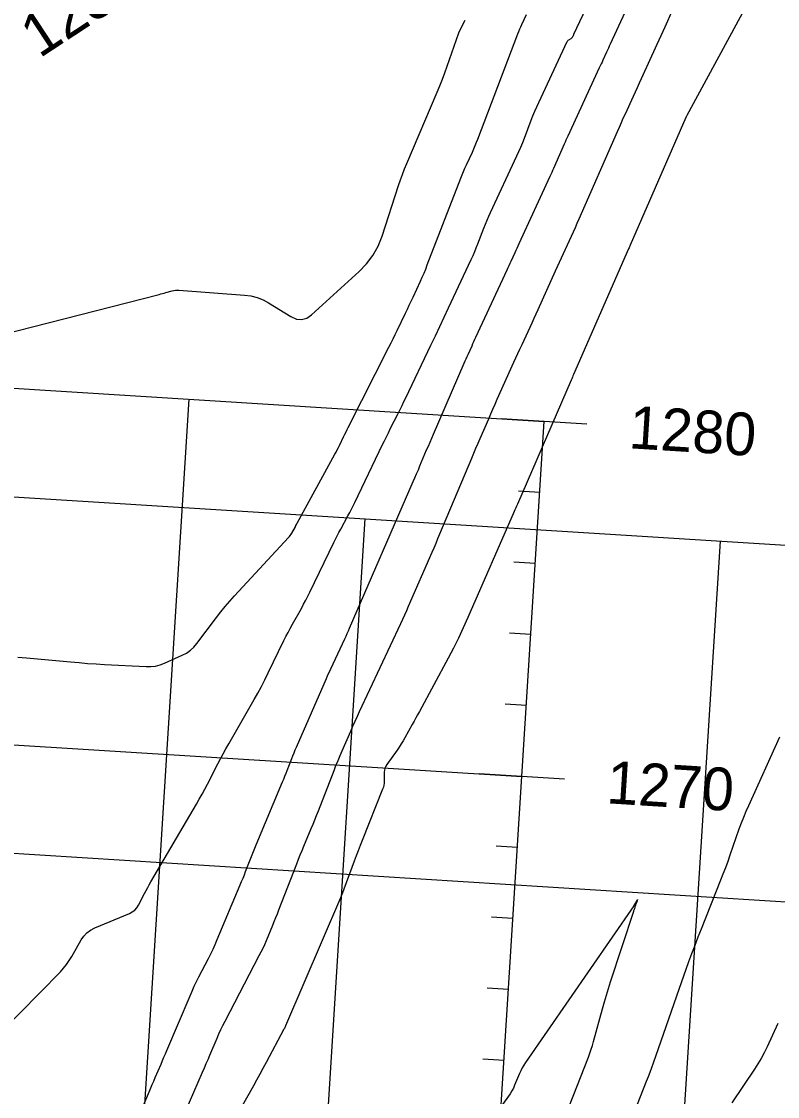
# Model space of a CAD drawing. Extents: x 658976 to 668726, y 639543 to 647196.
# Drawn here: x 661838.3 to 661944.5, y 642005.3 to 642156.4 of the extents above; entities that cross this region are included whole.
import ezdxf

# ---------------------------------------------------------------- set-up
doc = ezdxf.new("R2010")
doc.units = 0
for name, color, linetype in [('Ex_Contour Labels', 7, 'Continuous'), ('Ex_Major Contours', 7, 'Continuous'), ('Ex_Minor Contours', 7, 'Continuous'), ('R_Axis', 7, 'Continuous'), ('R_Axis Annot', 7, 'Continuous'), ('R_Grid', 7, 'Continuous')]:
    doc.layers.add(name, color=color, linetype=linetype)

msp = doc.modelspace()

# ---------------------------------------------------------------- linework, layer by layer
at = {"layer": 'Ex_Major Contours'}
msp.add_lwpolyline([(661912.02, 641995.73), (661917.97, 642010.88), (661918.18, 642011.43), (661918.37, 642011.98), (661918.54, 642012.53), (661918.7, 642013.09), (661919.95, 642017.69), (661920.22, 642018.64), (661920.5, 642019.59), (661920.79, 642020.53), (661921.09, 642021.47), (661924.34, 642031.39), (661924.37, 642031.49), (661924.41, 642031.58), (661924.44, 642031.68), (661924.47, 642031.78), (661924.59, 642032.17), (661924.62, 642032.26), (661924.65, 642032.36), (661924.68, 642032.45), (661924.72, 642032.54), (661924.85, 642032.92), (661924.87, 642032.99), (661924.88, 642033.02), (661924.85, 642033), (661924.81, 642032.94), (661924.4, 642032.3), (661924.39, 642032.29), (661924.39, 642032.28), (661924.38, 642032.27), (661924.38, 642032.26), (661924.36, 642032.2), (661924.36, 642032.19), (661924.35, 642032.18), (661924.35, 642032.17), (661924.34, 642032.16), (661909.15, 642010.12), (661908.91, 642009.75), (661908.68, 642009.37), (661908.48, 642008.97), (661908.3, 642008.57), (661907.6, 642006.92), (661907.42, 642006.52), (661907.21, 642006.13), (661906.98, 642005.74), (661906.73, 642005.38), (661901.65, 641998.3)], dxfattribs=at)
at = {"layer": 'Ex_Minor Contours'}
for points in [[(661832.29, 642011.27), (661843.76, 642022.89), (661844.21, 642023.39), (661844.63, 642023.9), (661845.01, 642024.45), (661845.36, 642025.02), (661846.68, 642027.36), (661847.05, 642027.9), (661847.48, 642028.36), (661847.99, 642028.75), (661848.58, 642029.05), (661853.46, 642031.09), (661853.86, 642031.29), (661854.21, 642031.56), (661854.5, 642031.88), (661854.74, 642032.26), (661855.6, 642033.9), (661855.81, 642034.31), (661856.03, 642034.71), (661856.26, 642035.12), (661856.49, 642035.52), (661862.88, 642046.44), (661863.28, 642047.14), (661863.67, 642047.83), (661864.05, 642048.54), (661864.42, 642049.25), (661865.89, 642052.09), (661866.26, 642052.8), (661866.63, 642053.51), (661867.02, 642054.21), (661867.42, 642054.91), (661871, 642061.14), (661871.52, 642062.06), (661872.02, 642062.99), (661872.5, 642063.93), (661872.97, 642064.88), (661875.17, 642069.43), (661875.45, 642070.01), (661875.75, 642070.58), (661876.05, 642071.15), (661876.37, 642071.72), (661877.64, 642073.96), (661877.95, 642074.53), (661878.26, 642075.1), (661878.55, 642075.67), (661878.84, 642076.25), (661882.19, 642083.23), (661882.42, 642083.7), (661882.66, 642084.17), (661882.91, 642084.64), (661883.16, 642085.11), (661884.17, 642086.96), (661884.42, 642087.42), (661884.67, 642087.89), (661884.91, 642088.36), (661885.14, 642088.83), (661889.04, 642096.97), (661889.3, 642097.52), (661889.57, 642098.07), (661889.85, 642098.62), (661890.12, 642099.17), (661891.23, 642101.36), (661891.51, 642101.91), (661891.78, 642102.46), (661892.05, 642103.01), (661892.31, 642103.56), (661895.84, 642110.94), (661896.47, 642112.25), (661897.09, 642113.57), (661897.71, 642114.88), (661898.32, 642116.19), (661901.5, 642123.01), (661901.75, 642123.55), (661901.99, 642124.1), (661902.21, 642124.64), (661902.43, 642125.2), (661903.28, 642127.41), (661903.5, 642127.97), (661903.73, 642128.51), (661903.97, 642129.06), (661904.21, 642129.6), (661907.93, 642137.56), (661908.21, 642138.17), (661908.48, 642138.79), (661908.73, 642139.42), (661908.98, 642140.05), (661909.94, 642142.57), (661910.18, 642143.2), (661910.44, 642143.83), (661910.71, 642144.45), (661910.99, 642145.06), (661914.99, 642153.62), (661915.03, 642153.7), (661915.08, 642153.76), (661915.14, 642153.82), (661915.21, 642153.86), (661915.54, 642154.06), (661915.59, 642154.09), (661915.64, 642154.13), (661915.67, 642154.18), (661915.71, 642154.23), (661915.82, 642154.43), (661915.85, 642154.49), (661915.88, 642154.54), (661915.91, 642154.59), (661915.93, 642154.65), (661920.21, 642163.81)], [(661925.45, 642162.82), (661921.03, 642153.26), (661920.9, 642152.98), (661920.77, 642152.71), (661920.64, 642152.43), (661920.52, 642152.15), (661920.01, 642151.03), (661919.89, 642150.75), (661919.76, 642150.47), (661919.63, 642150.19), (661919.5, 642149.91), (661915.07, 642140.33), (661914.94, 642140.05), (661914.81, 642139.77), (661914.68, 642139.48), (661914.56, 642139.2), (661913.07, 642135.79), (661912.94, 642135.5), (661912.82, 642135.22), (661912.69, 642134.93), (661912.56, 642134.65), (661908.17, 642125.17), (661908.03, 642124.86), (661907.89, 642124.56), (661907.75, 642124.25), (661907.61, 642123.94), (661907.06, 642122.72), (661906.92, 642122.41), (661906.78, 642122.11), (661906.64, 642121.8), (661906.5, 642121.5), (661902.12, 642112.04), (661901.98, 642111.73), (661901.84, 642111.43), (661901.7, 642111.13), (661901.57, 642110.82), (661901.02, 642109.6), (661900.88, 642109.3), (661900.75, 642109), (661900.61, 642108.69), (661900.48, 642108.38), (661896.14, 642098.4), (661895.9, 642097.84), (661895.66, 642097.29), (661895.43, 642096.73), (661895.19, 642096.17), (661894.25, 642093.94), (661894.02, 642093.39), (661893.78, 642092.83), (661893.54, 642092.27), (661893.3, 642091.72), (661884.36, 642071.11), (661884.2, 642070.74), (661884.03, 642070.37), (661883.87, 642070.01), (661883.7, 642069.65), (661881.72, 642065.43), (661881.56, 642065.09), (661881.41, 642064.75), (661881.25, 642064.41), (661881.1, 642064.07), (661876.91, 642054.42), (661876.73, 642054.01), (661876.56, 642053.61), (661876.4, 642053.2), (661876.24, 642052.79), (661875.6, 642051.14), (661875.44, 642050.73), (661875.27, 642050.32), (661875.11, 642049.91), (661874.94, 642049.51), (661871.23, 642040.67), (661871.04, 642040.21), (661870.85, 642039.74), (661870.66, 642039.27), (661870.48, 642038.8), (661869.75, 642036.92), (661869.57, 642036.45), (661869.38, 642035.99), (661869.19, 642035.52), (661869, 642035.05), (661865.77, 642027.35), (661865.48, 642026.68), (661865.18, 642026.01), (661864.86, 642025.35), (661864.53, 642024.7), (661863.17, 642022.11), (661862.84, 642021.45), (661862.52, 642020.8), (661862.22, 642020.13), (661861.93, 642019.46), (661858.68, 642011.78), (661858.48, 642011.3), (661858.27, 642010.82), (661858.07, 642010.34), (661857.86, 642009.86), (661857.03, 642007.95), (661856.83, 642007.47), (661856.62, 642006.99), (661856.42, 642006.51), (661856.22, 642006.03), (661852.96, 641998.34)], [(661940.78, 642159.84), (661931.8, 642143.23), (661931.76, 642143.15), (661931.72, 642143.08), (661931.69, 642143.01), (661931.66, 642142.94), (661923.85, 642125.01), (661923.79, 642124.88), (661923.73, 642124.75), (661923.68, 642124.61), (661923.62, 642124.48), (661915.87, 642106.81), (661915.79, 642106.62), (661915.71, 642106.43), (661915.62, 642106.24), (661915.54, 642106.04), (661907.98, 642088.58), (661907.87, 642088.32), (661907.76, 642088.07), (661907.65, 642087.82), (661907.54, 642087.57), (661901.04, 642072.65), (661900.39, 642071.2), (661899.71, 642069.77), (661899, 642068.34), (661898.26, 642066.94), (661894.22, 642059.47), (661893.97, 642059.01), (661893.72, 642058.55), (661893.46, 642058.09), (661893.21, 642057.63), (661892.18, 642055.78), (661891.92, 642055.34), (661891.66, 642054.9), (661891.37, 642054.47), (661891.08, 642054.04), (661889.64, 642052.02), (661889.48, 642051.77), (661889.37, 642051.5), (661889.3, 642051.22), (661889.28, 642050.92), (661889.28, 642049.71), (661889.26, 642049.4), (661889.22, 642049.11), (661889.15, 642048.82), (661889.05, 642048.53), (661886.18, 642041.33), (661885.9, 642040.61), (661885.62, 642039.89), (661885.34, 642039.17), (661885.07, 642038.44), (661883.25, 642033.59), (661883.22, 642033.51), (661883.18, 642033.42), (661883.15, 642033.34), (661883.11, 642033.25), (661875.4, 642015.28), (661875.35, 642015.16), (661875.29, 642015.04), (661875.24, 642014.92), (661875.17, 642014.8), (661872.67, 642010.11), (661872.23, 642009.29), (661871.79, 642008.47), (661871.34, 642007.66), (661870.88, 642006.84), (661868.34, 642002.31)], [(661837.78, 642067.08), (661838.98, 642067.01), (661845.2, 642066.43), (661846.39, 642066.33), (661847.58, 642066.23), (661848.78, 642066.15), (661849.98, 642066.08), (661855.8, 642065.77), (661856.47, 642065.77), (661857.13, 642065.85), (661857.78, 642066.01), (661858.4, 642066.25), (661860.89, 642067.37), (661861.49, 642067.68), (661862.03, 642068.06), (661862.52, 642068.51), (661862.95, 642069.02), (661865.71, 642072.68), (661866.32, 642073.46), (661866.94, 642074.23), (661867.59, 642074.98), (661868.25, 642075.72), (661875.83, 642083.94), (661875.96, 642084.08), (661876.07, 642084.22), (661876.18, 642084.38), (661876.27, 642084.54), (661876.78, 642085.43), (661876.8, 642085.47), (661876.82, 642085.51), (661876.84, 642085.55), (661876.86, 642085.59), (661876.94, 642085.76), (661876.96, 642085.8), (661876.98, 642085.84), (661877.01, 642085.88), (661877.03, 642085.92), (661882.35, 642095.61), (661882.52, 642095.92), (661882.68, 642096.23), (661882.84, 642096.55), (661882.99, 642096.86), (661883.6, 642098.14), (661883.75, 642098.45), (661883.91, 642098.77), (661884.07, 642099.08), (661884.22, 642099.4), (661889.94, 642110.68), (661890.24, 642111.26), (661890.53, 642111.85), (661890.81, 642112.44), (661891.1, 642113.03), (661892.26, 642115.47), (661892.53, 642116.02), (661892.8, 642116.58), (661893.06, 642117.14), (661893.32, 642117.7), (661894.37, 642119.95), (661894.62, 642120.51), (661894.87, 642121.08), (661895.11, 642121.65), (661895.33, 642122.22), (661900.04, 642134.44), (661900.22, 642134.91), (661900.41, 642135.37), (661900.61, 642135.82), (661900.82, 642136.28), (661901.66, 642138.08), (661901.87, 642138.54), (661902.06, 642139), (661902.25, 642139.46), (661902.43, 642139.92), (661908.05, 642154.73), (661908.18, 642155.06), (661908.32, 642155.39), (661908.46, 642155.71), (661908.6, 642156.03), (661909.26, 642157.44)], [(661929.81, 642158.06), (661928.69, 642155.65), (661928.41, 642155.04), (661928.14, 642154.44), (661927.86, 642153.84), (661927.59, 642153.23), (661925.4, 642148.38), (661925.12, 642147.76), (661924.84, 642147.14), (661924.55, 642146.52), (661924.27, 642145.9), (661923.12, 642143.42), (661922.83, 642142.8), (661922.55, 642142.18), (661922.27, 642141.55), (661922, 642140.93), (661916.63, 642128.64), (661916.36, 642128.03), (661916.09, 642127.42), (661915.81, 642126.81), (661915.53, 642126.21), (661914.41, 642123.79), (661914.14, 642123.19), (661913.86, 642122.58), (661913.58, 642121.97), (661913.31, 642121.37), (661910.86, 642115.92), (661910.58, 642115.3), (661910.3, 642114.68), (661910.02, 642114.06), (661909.73, 642113.45), (661908.59, 642110.98), (661908.3, 642110.36), (661908.02, 642109.74), (661907.74, 642109.12), (661907.46, 642108.5), (661905.12, 642103.31), (661904.81, 642102.62), (661904.51, 642101.93), (661904.21, 642101.24), (661903.91, 642100.56), (661902.71, 642097.8), (661902.41, 642097.11), (661902.11, 642096.42), (661901.82, 642095.72), (661901.53, 642095.03), (661897.06, 642084.38), (661896.78, 642083.74), (661896.51, 642083.09), (661896.23, 642082.44), (661895.95, 642081.8), (661892.66, 642074.22), (661892.39, 642073.6), (661892.12, 642072.99), (661891.84, 642072.38), (661891.55, 642071.76), (661885.77, 642059.42), (661885.45, 642058.74), (661885.13, 642058.05), (661884.82, 642057.36), (661884.52, 642056.67), (661883.31, 642053.9), (661883.02, 642053.21), (661882.73, 642052.51), (661882.44, 642051.81), (661882.17, 642051.1), (661879.97, 642045.44), (661879.72, 642044.81), (661879.48, 642044.19), (661879.22, 642043.57), (661878.97, 642042.96), (661877.93, 642040.49), (661877.68, 642039.88), (661877.43, 642039.26), (661877.18, 642038.64), (661876.94, 642038.02), (661874.43, 642031.53), (661874.22, 642030.98), (661874, 642030.44), (661873.78, 642029.9), (661873.56, 642029.37), (661872.66, 642027.22), (661872.43, 642026.68), (661872.19, 642026.15), (661871.94, 642025.63), (661871.67, 642025.11), (661866.85, 642015.88), (661866.55, 642015.3), (661866.27, 642014.71), (661865.99, 642014.12), (661865.73, 642013.52), (661864.72, 642011.12), (661864.46, 642010.52), (661864.21, 642009.92), (661863.95, 642009.32), (661863.69, 642008.72), (661861.27, 642003.11)], [(661830.99, 642111.27), (661857.64, 642118.09), (661857.87, 642118.15), (661858.1, 642118.21), (661858.33, 642118.27), (661858.56, 642118.33), (661859.48, 642118.59), (661859.71, 642118.64), (661859.94, 642118.67), (661860.17, 642118.68), (661860.41, 642118.68), (661869.65, 642118), (661870.54, 642117.88), (661871.41, 642117.66), (661872.24, 642117.33), (661873.03, 642116.9), (661876.15, 642114.96), (661876.92, 642114.62), (661877.66, 642114.54), (661878.38, 642114.75), (661879.07, 642115.23), (661885.75, 642121.3), (661886.8, 642122.38), (661887.68, 642123.57), (661888.4, 642124.86), (661888.96, 642126.26), (661891.28, 642133.39), (661891.55, 642134.17), (661891.83, 642134.95), (661892.13, 642135.72), (661892.44, 642136.49), (661896.7, 642146.5), (661897.08, 642147.41), (661897.44, 642148.32), (661897.79, 642149.25), (661898.12, 642150.17), (661899.43, 642153.92), (661899.78, 642154.84), (661900.19, 642155.74), (661900.64, 642156.61)], [(661923.29, 642000.21), (661926.15, 642007.51), (661926.4, 642008.15), (661926.64, 642008.79), (661926.88, 642009.44), (661927.11, 642010.09), (661928.89, 642015.21), (661929.27, 642016.28), (661929.64, 642017.35), (661930.02, 642018.42), (661930.39, 642019.49), (661932.1, 642024.31), (661932.52, 642025.47), (661932.95, 642026.62), (661933.38, 642027.77), (661933.84, 642028.91), (661936.58, 642035.78), (661936.93, 642036.66), (661937.26, 642037.54), (661937.59, 642038.42), (661937.9, 642039.31), (661939.17, 642042.95), (661939.47, 642043.79), (661939.8, 642044.62), (661940.14, 642045.44), (661940.5, 642046.26), (661944.88, 642055.89)], [(661944.58, 642015.59), (661943.07, 642012.31), (661942.68, 642011.49), (661942.25, 642010.7), (661941.8, 642009.92), (661941.31, 642009.17), (661938.14, 642004.48)]]:
    msp.add_lwpolyline(points, dxfattribs=at)
at = {"layer": 'R_Axis'}
for p, q in [((661899.22, 641900.61), (661911.75, 642100.21)), ((661917.74, 642099.84), (661905.77, 642100.59)), ((661911.13, 642090.23), (661908.13, 642090.42)), ((661910.5, 642080.25), (661907.51, 642080.44)), ((661909.87, 642070.27), (661906.88, 642070.46)), ((661909.25, 642060.29), (661906.25, 642060.48)), ((661914.61, 642049.94), (661902.63, 642050.69)), ((661907.99, 642040.33), (661905, 642040.52)), ((661907.37, 642030.35), (661904.37, 642030.54)), ((661906.74, 642020.37), (661903.75, 642020.56)), ((661906.11, 642010.39), (661903.12, 642010.58))]:
    msp.add_line(p, q, dxfattribs=at)
at = {"layer": 'R_Grid'}
for p, q in [((660414.7, 642194.23), (661911.75, 642100.21)), ((660411.57, 642144.33), (661908.62, 642050.31)), ((661849.32, 641903.74), (661861.85, 642103.35)), ((661637.1, 642102.2), (663134.15, 642008.18)), ((661899.22, 641900.61), (661911.75, 642100.21)), ((661870.94, 641837.02), (661886.61, 642086.53)), ((661920.84, 641833.88), (661936.51, 642083.39)), ((661633.97, 642052.3), (663131.02, 641958.27))]:
    msp.add_line(p, q, dxfattribs=at)

# ---------------------------------------------------------------- texts
at = {"layer": 'Ex_Contour Labels'}
msp.add_text('1255', height=6, rotation=33.3111, dxfattribs=at).set_placement((661840.82, 642151.21))
at = {"layer": 'R_Axis Annot'}
for s, p in [('1280', (661923.54, 642096.47)), ('1270', (661920.41, 642046.57))]:
    msp.add_text(s, height=6, rotation=356.4063, dxfattribs=at).set_placement(p)

doc.saveas('drawing.dxf')
